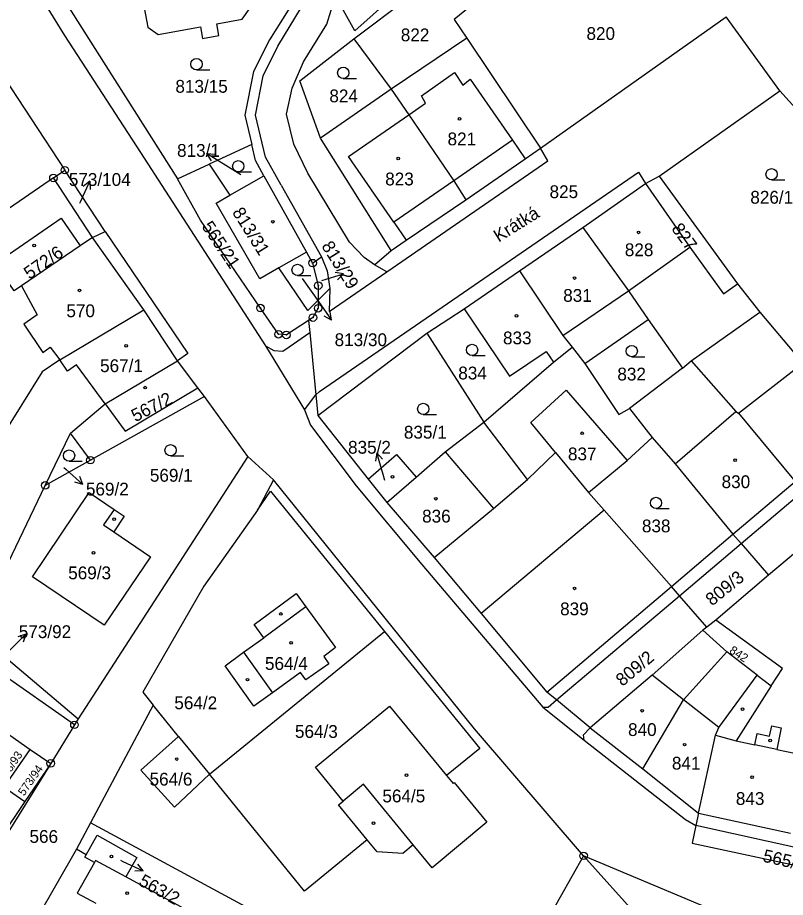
# Model space of a CAD drawing. Extents: x -776701 to -776081, y -974398 to -973771.
# Drawn here: x -776342.5 to -776240.6, y -974065.8 to -973949 of the extents above; entities that cross this region are included whole.
import ezdxf

# ---------------------------------------------------------------- set-up
doc = ezdxf.new("R2010")
doc.units = 0
for name, color, linetype in [('Hranice parcel', 7, 'Continuous'), ('Parcelní čísla', 7, 'Continuous'), ('Pop  PČ popisy', 7, 'Continuous'), ('Vnitřní kresba', 7, 'Continuous'), ('Značky bodu BP', 7, 'Continuous'), ('Značky budov', 7, 'Continuous'), ('Značky kultur', 7, 'Continuous')]:
    doc.layers.add(name, color=color, linetype=linetype)

msp = doc.modelspace()

# ---------------------------------------------------------------- linework, layer by layer
at = {"layer": 'Hranice parcel'}
for p, q in [((-776297.88, -973951.84), (-776284.08, -973941.43)), ((-776338.75, -973942.85), (-776321.28, -973970.41)), ((-776273.08, -973966.36), (-776248.44, -973948.9)), ((-776241.31, -973958.73), (-776248.44, -973948.9)), ((-776297.88, -973951.84), (-776292.9, -973958.5)), ((-776282.89, -973951.76), (-776292.9, -973958.5)), ((-776282.89, -973951.76), (-776273.08, -973966.36)), ((-776346.46, -973953.73), (-776336.24, -973969.27)), ((-776292.9, -973958.5), (-776302.3, -973965)), ((-776257.34, -973970.07), (-776241.31, -973958.73)), ((-776311.42, -973965.87), (-776317.09, -973968.48)), ((-776292.91, -973979.92), (-776302.3, -973965)), ((-776337.75, -973970.3), (-776336.24, -973969.27)), ((-776321.28, -973970.41), (-776317.09, -973968.48)), ((-776317.09, -973968.48), (-776314.32, -973972.59)), ((-776332.57, -973978.19), (-776337.75, -973970.3)), ((-776318.24, -973975.91), (-776321.28, -973970.41)), ((-776314.32, -973972.59), (-776309.8, -973970.01)), ((-776309.8, -973970.01), (-776304.16, -973980.15)), ((-776259.16, -973971.03), (-776257.34, -973970.07)), ((-776257.34, -973970.07), (-776246.94, -973984.38)), ((-776267.49, -973976.87), (-776259.16, -973971.03)), ((-776275.87, -973982.65), (-776267.49, -973976.87)), ((-776332.57, -973978.19), (-776334.21, -973979.31)), ((-776325.75, -973987.82), (-776332.57, -973978.19)), ((-776295.13, -973981.83), (-776292.91, -973979.92)), ((-776304.16, -973980.15), (-776307.81, -973982.25)), ((-776304.16, -973980.15), (-776303.35, -973981.61)), ((-776283.21, -973987.69), (-776275.87, -973982.65)), ((-776246.94, -973984.38), (-776243.98, -973988.1)), ((-776301.05, -973985), (-776302.6, -973986.53)), ((-776302.6, -973986.53), (-776302.61, -973987.61)), ((-776336.89, -973994.45), (-776325.75, -973987.82)), ((-776321.3, -973994.6), (-776325.75, -973987.82)), ((-776288.2, -973990.91), (-776283.21, -973987.69)), ((-776253.07, -973994.57), (-776243.98, -973988.1)), ((-776267.2, -973994.95), (-776258.81, -973989.08)), ((-776258.81, -973989.08), (-776254.25, -973995.57)), ((-776302.67, -974001.86), (-776288.2, -973990.91)), ((-776288.2, -973990.91), (-776280.61, -974002.73)), ((-776271.38, -973994.77), (-776268.9, -973992.75)), ((-776268.9, -973992.75), (-776267.2, -973994.95)), ((-776330.9, -974000.3), (-776321.3, -973994.6)), ((-776280.61, -974002.73), (-776271.38, -973994.77)), ((-776254.25, -973995.57), (-776253.07, -973994.57)), ((-776254.25, -973995.57), (-776261.3, -974000.9)), ((-776317.7, -973999.3), (-776332.85, -974007.77)), ((-776311.96, -974007.29), (-776317.7, -973999.3)), ((-776335.5, -974004.17), (-776330.9, -974000.3)), ((-776261.3, -974000.9), (-776258.29, -974004.76)), ((-776302.67, -974001.86), (-776295.97, -974010.29)), ((-776274.81, -974010.35), (-776280.61, -974002.73)), ((-776338.84, -974011.12), (-776335.5, -974004.17)), ((-776332.85, -974007.77), (-776335.5, -974004.17)), ((-776332.85, -974007.77), (-776338.84, -974011.12)), ((-776311.96, -974007.29), (-776334.46, -974042.11)), ((-776308.52, -974010.36), (-776311.96, -974007.29)), ((-776308.52, -974010.36), (-776310.67, -974014.4)), ((-776295.97, -974010.29), (-776293.49, -974013.38)), ((-776293.49, -974013.38), (-776289.58, -974010.03)), ((-776348.16, -974030.54), (-776338.84, -974011.12)), ((-776247.57, -974017.58), (-776239.27, -974010.62)), ((-776293.49, -974013.38), (-776287.2, -974020.7)), ((-776231.58, -974013.49), (-776242.81, -974023.05)), ((-776255.71, -974024.55), (-776247.57, -974017.58)), ((-776242.81, -974023.05), (-776249.83, -974029.02)), ((-776272.25, -974038.56), (-776255.71, -974024.55)), ((-776249.83, -974029.02), (-776251.01, -974029.93)), ((-776251.01, -974029.93), (-776251.54, -974030.34)), ((-776248.36, -974033.23), (-776251.54, -974030.34)), ((-776348.16, -974030.54), (-776334.46, -974042.11)), ((-776317.05, -974049.45), (-776293.78, -974030.52)), ((-776334.96, -974042.91), (-776348.94, -974033.12)), ((-776244.32, -974036.32), (-776248.36, -974033.23)), ((-776324.49, -974040.31), (-776332.81, -974055.91)), ((-776321.13, -974044.44), (-776324.49, -974040.31)), ((-776334.96, -974042.91), (-776338.11, -974048.02)), ((-776334.46, -974042.11), (-776334.96, -974042.91)), ((-776343.54, -974044.26), (-776340.85, -974046.16)), ((-776266.49, -974043.3), (-776259.49, -974048.74)), ((-776321.13, -974044.44), (-776317.05, -974049.45)), ((-776344.27, -974051.19), (-776340.85, -974046.16)), ((-776340.85, -974046.16), (-776338.11, -974048.02)), ((-776338.11, -974048.02), (-776344.68, -974058.65)), ((-776338.11, -974048.02), (-776341.55, -974053.07)), ((-776259.49, -974048.74), (-776252.12, -974054.65)), ((-776317.05, -974049.45), (-776321.68, -974053.83)), ((-776344.27, -974051.19), (-776341.55, -974053.07)), ((-776296.1, -974058.19), (-776299.93, -974053.54)), ((-776252.12, -974054.65), (-776252.47, -974056.28)), ((-776252.12, -974054.65), (-776239.9, -974057.27)), ((-776332.81, -974055.91), (-776334.7, -974059.4)), ((-776309.4, -974068.57), (-776332.81, -974055.91)), ((-776294.79, -974059.76), (-776296.1, -974058.19)), ((-776334.7, -974059.4), (-776344.3, -974076.22)), ((-776333.4, -974060.17), (-776334.7, -974059.4)), ((-776267.37, -974060.3), (-776282.47, -974086.79)), ((-776248.62, -974068.16), (-776267.37, -974060.3)), ((-776246.97, -974083.03), (-776267.37, -974060.3))]:
    msp.add_line(p, q, dxfattribs=at)
for points in [[(-776313.98, -973911.05), (-776297.73, -973912.06), (-776288.32, -973927.36), (-776286.35, -973940.59), (-776297.76, -973950.76), (-776300.32, -973946.11)], [(-776348.8, -973929.48), (-776343.01, -973940.47), (-776336.28, -973951.4), (-776326.2, -973966.93), (-776309.58, -973992.58), (-776304.42, -974001.08), (-776303.62, -974003.12), (-776297.56, -974011.17), (-776288.84, -974021.6), (-776272.77, -974040.55), (-776267.29, -974044.95), (-776253.84, -974055.49), (-776252.47, -974056.28)], [(-776327.4, -973940.82), (-776326.45, -973946.13), (-776326.01, -973946.05), (-776325.24, -973950.29), (-776323.84, -973951.26), (-776318.22, -973950.24), (-776317.95, -973951.77), (-776315.78, -973951.38), (-776316.05, -973949.85), (-776312.7, -973949.24), (-776311.73, -973947.84), (-776312.5, -973943.6), (-776311.81, -973943.48), (-776304.89, -973942.24)], [(-776304.89, -973942.24), (-776305.41, -973945.33), (-776306.38, -973947.66), (-776309.08, -973951.97), (-776311.19, -973956.17), (-776312.36, -973961.96), (-776311.42, -973965.87)], [(-776295.13, -973981.83), (-776296.49, -973980.88), (-776298.45, -973978.83), (-776303.97, -973969.66), (-776305.82, -973965.81), (-776306.81, -973961.85), (-776306.08, -973958.37), (-776304.57, -973954.89), (-776301.44, -973949.87), (-776300.32, -973946.11)], [(-776280.81, -973946.19), (-776284.56, -973949.27), (-776282.89, -973951.76)], [(-776302.3, -973965), (-776305.05, -973957.4), (-776297.88, -973951.84)], [(-776292.9, -973958.5), (-776290.55, -973961.91), (-776284.59, -973970.68), (-776283.02, -973973.23)], [(-776230.92, -974003.68), (-776213.75, -973989.29), (-776241.31, -973958.73)], [(-776309.8, -973970.01), (-776310.91, -973967.99), (-776311.42, -973965.87)], [(-776283.02, -973973.23), (-776275.12, -973967.75), (-776273.08, -973966.36)], [(-776332.57, -973978.19), (-776330.9, -973977.4), (-776336.24, -973969.27)], [(-776337.75, -973970.3), (-776338.32, -973970.69), (-776348.3, -973977.53), (-776374.53, -974010.37)], [(-776259.16, -973971.03), (-776253.26, -973979.51), (-776248.81, -973985.69), (-776246.94, -973984.38)], [(-776307.81, -973982.25), (-776310.35, -973983.7), (-776316.15, -973973.64), (-776314.32, -973972.59)], [(-776292.91, -973979.92), (-776290.92, -973978.58), (-776283.02, -973973.23)], [(-776342.98, -973985.31), (-776345.48, -973981.66), (-776336.71, -973975.66), (-776334.21, -973979.31)], [(-776303.87, -973989.21), (-776306.83, -973991.14), (-776307.87, -973991.06), (-776310.26, -973987.58), (-776318.24, -973975.91)], [(-776267.49, -973976.87), (-776261.42, -973985.31), (-776258.81, -973989.08)], [(-776334.21, -973979.31), (-776342, -973984.63), (-776342.98, -973985.31)], [(-776303.35, -973981.61), (-776302.17, -973980.77), (-776301.41, -973982.63), (-776301.05, -973985)], [(-776302.6, -973986.53), (-776304, -973987.9), (-776307.81, -973982.25)], [(-776303.35, -973981.61), (-776302.59, -973984.6), (-776302.6, -973986.53)], [(-776301.05, -973985), (-776301.15, -973988.05), (-776293.49, -973982.77), (-776295.13, -973981.83)], [(-776275.87, -973982.65), (-776270.15, -973991.2), (-776268.9, -973992.75)], [(-776302.61, -973987.61), (-776303.3, -973988.84), (-776303.87, -973989.21)], [(-776283.21, -973987.69), (-776277.23, -973996.63), (-776272.33, -973993.35), (-776271.38, -973994.77)], [(-776243.98, -973988.1), (-776238.25, -973994.88), (-776230.92, -974003.68)], [(-776303.87, -973989.21), (-776303.72, -973990.83), (-776302.93, -973999.08), (-776302.67, -974001.86)], [(-776336.89, -973994.45), (-776339.24, -973996.03), (-776344.63, -974004.7)], [(-776330.9, -974000.3), (-776334.7, -973995.1), (-776335.9, -973995.95), (-776336.89, -973994.45)], [(-776317.7, -973999.3), (-776318.56, -973998.17), (-776321.3, -973994.6)], [(-776267.2, -973994.95), (-776262.7, -974001.7), (-776261.3, -974000.9)], [(-776253.07, -973994.57), (-776247.18, -974001.31), (-776246.82, -974001.54), (-776239.27, -974010.62)], [(-776289.58, -974010.03), (-776285.74, -974006.66), (-776280.61, -974002.73)], [(-776266.72, -974012.05), (-776261.58, -974007.81), (-776258.29, -974004.76)], [(-776258.29, -974004.76), (-776255.23, -974008.26), (-776247.57, -974017.58)], [(-776274.81, -974010.35), (-776271.09, -974006.74), (-776266.72, -974012.05)], [(-776295.97, -974010.29), (-776292.19, -974007.01), (-776289.58, -974010.03)], [(-776267.37, -974060.3), (-776281.86, -974043.45), (-776308.52, -974010.36)], [(-776287.2, -974020.7), (-776279.35, -974014.2), (-776274.81, -974010.35)], [(-776340.54, -974023.25), (-776332.99, -974012.08), (-776329.69, -974014.3), (-776328.36, -974015.19), (-776329.75, -974017.28), (-776324.86, -974020.59), (-776331.02, -974029.69), (-776340.54, -974023.25)], [(-776310.67, -974014.4), (-776308.92, -974011.9), (-776293.78, -974030.52)], [(-776266.72, -974012.05), (-776264.63, -974014.42), (-776255.71, -974024.55)], [(-776310.67, -974014.4), (-776317.77, -974024.51), (-776325.89, -974038.59), (-776324.49, -974040.31)], [(-776247.57, -974017.58), (-776246.47, -974018.84), (-776242.81, -974023.05)], [(-776287.2, -974020.7), (-776280.99, -974028.12), (-776272.25, -974038.56)], [(-776300.3, -974032.65), (-776301.87, -974033.84), (-776301.2, -974034.79), (-776304.23, -974036.93), (-776304.95, -974035.94), (-776308.67, -974038.65), (-776311.16, -974040.45), (-776314.95, -974035.08), (-776312.51, -974033.28), (-776309.82, -974031.36), (-776311.09, -974029.58), (-776305.51, -974025.48), (-776304.23, -974027.24), (-776300.3, -974032.65)], [(-776251.01, -974029.93), (-776254.65, -974025.76), (-776255.71, -974024.55)], [(-776244.32, -974036.32), (-776242.45, -974037.75), (-776240.95, -974035.41), (-776249.83, -974029.02)], [(-776251.54, -974030.34), (-776258.26, -974036.31), (-776266.49, -974043.3)], [(-776293.78, -974030.52), (-776281.16, -974046.04), (-776285.56, -974049.62)], [(-776259.49, -974048.74), (-776254.11, -974039.57), (-776248.36, -974033.23)], [(-776252.12, -974054.65), (-776249.88, -974044.26), (-776249.42, -974043.26), (-776244.32, -974036.32)], [(-776266.49, -974043.3), (-776270.99, -974039.59), (-776272.25, -974038.56)], [(-776299.93, -974053.54), (-776299.29, -974053.02), (-776302.98, -974048.54), (-776293.15, -974040.43), (-776285.56, -974049.62)], [(-776321.68, -974053.83), (-776326.17, -974048.92), (-776321.13, -974044.44)], [(-776296.1, -974058.19), (-776304.44, -974064.97), (-776317.05, -974049.45)], [(-776285.56, -974049.62), (-776284.68, -974050.68), (-776284.56, -974050.58), (-776280.21, -974055.85), (-776287.46, -974061.89), (-776289.98, -974058.83), (-776291.39, -974059.99), (-776294.79, -974059.76)], [(-776341.55, -974053.07), (-776344.92, -974058.03), (-776347.66, -974056.15)], [(-776252.47, -974056.28), (-776252.98, -974058.63), (-776229.18, -974063.72), (-776228.71, -974061.56)], [(-776333.4, -974060.17), (-776331.95, -974057.57), (-776326.69, -974060.51), (-776328.13, -974063.09)], [(-776332.31, -974061.19), (-776333.57, -974060.48), (-776333.4, -974060.17)], [(-776332.31, -974061.19), (-776334.6, -974065.25), (-776332.13, -974066.56)], [(-776328.13, -974063.09), (-776332.15, -974060.9), (-776332.31, -974061.19)], [(-776322.64, -974071.77), (-776320.25, -974067.39), (-776328.13, -974063.09)]]:
    msp.add_lwpolyline(points, dxfattribs=at)
at = {"layer": 'Pop  PČ popisy'}
for p, q in [((-776314.86, -973968.64), (-776317.41, -973967.05)), ((-776317.41, -973967.05), (-776316.29, -973967.16)), ((-776317.41, -973967.05), (-776316.82, -973968.01)), ((-776312.87, -973969.89), (-776314.86, -973968.64)), ((-776334.16, -973973.47), (-776332.94, -973970.73)), ((-776332.94, -973970.73), (-776333.8, -973971.44)), ((-776332.94, -973970.73), (-776332.89, -973971.85)), ((-776334.25, -973973.66), (-776334.16, -973973.47)), ((-776302.11, -973983.92), (-776299.24, -973983.04)), ((-776299.24, -973983.04), (-776300.34, -973982.86)), ((-776299.24, -973983.04), (-776300.05, -973983.81)), ((-776304.71, -973983.67), (-776302.57, -973986.71)), ((-776302.11, -973983.92), (-776302.12, -973983.92)), ((-776302.57, -973986.71), (-776300.85, -973989.17)), ((-776300.85, -973989.17), (-776301.01, -973988.06)), ((-776300.85, -973989.17), (-776301.83, -973988.64)), ((-776294.81, -974006.81), (-776295.01, -974007.91)), ((-776293.98, -974009.69), (-776294.81, -974006.81)), ((-776294.81, -974006.81), (-776294.05, -974007.63)), ((-776336.36, -974008.73), (-776336.07, -974008.99)), ((-776336.07, -974008.99), (-776333.84, -974011)), ((-776333.84, -974011), (-776334.25, -974009.96)), ((-776293.76, -974010.45), (-776293.98, -974009.69)), ((-776333.84, -974011), (-776334.92, -974010.7)), ((-776343.55, -974032.99), (-776341.43, -974030.87)), ((-776341.43, -974030.87), (-776342.49, -974031.22)), ((-776341.43, -974030.87), (-776341.78, -974031.93)), ((-776328.86, -974060.89), (-776328.56, -974061.03)), ((-776328.56, -974061.03), (-776325.84, -974062.3)), ((-776325.84, -974062.3), (-776326.54, -974061.42)), ((-776325.84, -974062.3), (-776326.96, -974062.33))]:
    msp.add_line(p, q, dxfattribs=at)
at = {"layer": 'Vnitřní kresba'}
for p, q in [((-776307.95, -973952.83), (-776304.82, -973947.64)), ((-776309.89, -973956.74), (-776307.95, -973952.83)), ((-776310.93, -973961.96), (-776309.89, -973956.74)), ((-776288.9, -973959.4), (-776284.53, -973956.3)), ((-776284.53, -973956.3), (-776283.4, -973958)), ((-776283.4, -973958), (-776282.45, -973957.2)), ((-776282.45, -973957.2), (-776276.79, -973965.28)), ((-776288.34, -973960.39), (-776288.9, -973959.4)), ((-776290.55, -973961.91), (-776288.34, -973960.39)), ((-776309.58, -973967.56), (-776310.93, -973961.96)), ((-776298.6, -973967.47), (-776290.55, -973961.91)), ((-776276.79, -973965.28), (-776284.59, -973970.68)), ((-776276.79, -973965.28), (-776275.12, -973967.75)), ((-776272.13, -973968.03), (-776273.08, -973966.36)), ((-776307.52, -973971.26), (-776309.58, -973967.56)), ((-776292.58, -973976.18), (-776298.6, -973967.47)), ((-776293.49, -973982.77), (-776272.13, -973968.03)), ((-776302.45, -973998.67), (-776260.07, -973969.53)), ((-776260.07, -973969.53), (-776259.16, -973971.03)), ((-776284.59, -973970.68), (-776292.58, -973976.18)), ((-776307.52, -973971.26), (-776302.17, -973980.77)), ((-776292.58, -973976.18), (-776290.92, -973978.58)), ((-776330.9, -973977.4), (-776319.9, -973993.6)), ((-776261.42, -973985.31), (-776253.26, -973979.51)), ((-776342, -973984.63), (-776339.89, -973988.49)), ((-776270.15, -973991.2), (-776261.42, -973985.31)), ((-776339.89, -973988.49), (-776341.67, -973989.72)), ((-776341.67, -973989.72), (-776339.18, -973993.46)), ((-776246.47, -974018.84), (-776212.73, -973990.29)), ((-776339.18, -973993.46), (-776338.18, -973992.79)), ((-776338.18, -973992.79), (-776336.89, -973994.45)), ((-776319.9, -973993.6), (-776321.3, -973994.6)), ((-776246.82, -974001.54), (-776238.25, -973994.88)), ((-776328.24, -974003.93), (-776318.56, -973998.17)), ((-776302.45, -973998.67), (-776302.93, -973999.08)), ((-776274.36, -974002.77), (-776269.67, -973998.49)), ((-776269.67, -973998.49), (-776261.58, -974007.81)), ((-776304.42, -974001.08), (-776302.93, -973999.08)), ((-776330.9, -974000.3), (-776328.24, -974003.93)), ((-776255.23, -974008.26), (-776247.18, -974001.31)), ((-776271.09, -974006.74), (-776274.36, -974002.77)), ((-776285.74, -974006.66), (-776279.35, -974014.2)), ((-776264.63, -974014.42), (-776280.99, -974028.12)), ((-776254.65, -974025.76), (-776246.47, -974018.84)), ((-776270.99, -974039.59), (-776254.65, -974025.76)), ((-776304.23, -974027.24), (-776309.82, -974031.36)), ((-776312.51, -974033.28), (-776308.67, -974038.65)), ((-776254.11, -974039.57), (-776258.26, -974036.31)), ((-776242.45, -974037.75), (-776247.13, -974045.01)), ((-776249.42, -974043.26), (-776254.11, -974039.57)), ((-776242.68, -974044.41), (-776242.38, -974043.05)), ((-776242.38, -974043.05), (-776241.14, -974043.31)), ((-776267.39, -974044.25), (-776266.49, -974043.3)), ((-776267.29, -974044.95), (-776267.39, -974044.25)), ((-776249.88, -974044.26), (-776247.13, -974045.01)), ((-776244.63, -974045.54), (-776244.31, -974044.06)), ((-776244.31, -974044.06), (-776242.68, -974044.41)), ((-776241.14, -974043.31), (-776241.74, -974046.16)), ((-776247.13, -974045.01), (-776244.63, -974045.54)), ((-776241.74, -974046.16), (-776244.63, -974045.54)), ((-776241.74, -974046.16), (-776237.86, -974046.99)), ((-776296.61, -974050.8), (-776299.29, -974053.02)), ((-776289.98, -974058.83), (-776296.61, -974050.8)), ((-776228.69, -974061.51), (-776252.47, -974056.28))]:
    msp.add_line(p, q, dxfattribs=at)
for points in [[(-776309.58, -973992.58), (-776308.49, -973993.22), (-776307.31, -973993.31), (-776306.47, -973992.73), (-776303.72, -973990.83)], [(-776329.69, -974014.3), (-776331.09, -974016.37), (-776329.75, -974017.28)], [(-776272.77, -974040.55), (-776272.06, -974040.55), (-776270.99, -974039.59)]]:
    msp.add_lwpolyline(points, dxfattribs=at)
at = {"layer": 'Značky bodu BP'}
for centre, radius in [((-776336.24, -973969.27), 0.5), ((-776336.24, -973969.27), 0.0303), ((-776337.75, -973970.3), 0.5), ((-776337.75, -973970.3), 0.0303), ((-776303.35, -973981.61), 0.5), ((-776303.35, -973981.61), 0.0303), ((-776302.59, -973984.6), 0.5), ((-776302.59, -973984.6), 0.0303), ((-776310.26, -973987.58), 0.5), ((-776302.61, -973987.61), 0.5), ((-776310.26, -973987.58), 0.0303), ((-776302.61, -973987.61), 0.0303), ((-776303.3, -973988.84), 0.5), ((-776303.3, -973988.84), 0.0303), ((-776307.87, -973991.06), 0.5), ((-776306.83, -973991.14), 0.5), ((-776307.87, -973991.06), 0.0303), ((-776306.83, -973991.14), 0.0303), ((-776332.85, -974007.77), 0.5), ((-776332.85, -974007.77), 0.0303), ((-776338.84, -974011.12), 0.5), ((-776338.84, -974011.12), 0.0303), ((-776334.96, -974042.91), 0.5), ((-776334.96, -974042.91), 0.0303), ((-776338.11, -974048.02), 0.5), ((-776338.11, -974048.02), 0.0303), ((-776267.37, -974060.3), 0.5), ((-776267.37, -974060.3), 0.0303)]:
    msp.add_circle(centre, radius, dxfattribs=at)
at = {"layer": 'Značky budov'}
for centre in [(-776283.83, -973962.46), (-776291.97, -973967.71), (-776308.62, -973976.11), (-776260.07, -973977.53), (-776340.32, -973979.28), (-776268.56, -973983.59), (-776334.28, -973985.23), (-776276.27, -973988.62), (-776328.09, -973992.6), (-776325.58, -973998.14), (-776267.57, -974004.2), (-776247.27, -974007.77), (-776292.73, -974009.99), (-776286.98, -974012.89), (-776329.68, -974015.61), (-776332.42, -974020.07), (-776268.56, -974024.79), (-776307.57, -974028.19), (-776306.21, -974032.03), (-776311.98, -974036.91), (-776259.6, -974041.03), (-776246.26, -974040.82), (-776253.96, -974045.54), (-776242.61, -974044.98), (-776321.39, -974047.45), (-776290.89, -974049.6), (-776245.01, -974049.86), (-776295.25, -974055.96), (-776330.06, -974060.39), (-776327.96, -974065.26)]:
    msp.add_circle(centre, 0.175, dxfattribs=at)
at = {"layer": 'Značky kultur'}
for p, q in [((-776318.76, -973955.95), (-776317.01, -973955.95)), ((-776299.28, -973957.1), (-776297.53, -973957.1)), ((-776313.21, -973969.5), (-776311.46, -973969.5)), ((-776242.41, -973970.56), (-776240.66, -973970.56)), ((-776305.34, -973983.26), (-776303.59, -973983.26)), ((-776282.17, -973993.89), (-776280.42, -973993.89)), ((-776260.98, -973994.03), (-776259.23, -973994.03)), ((-776288.65, -974001.72), (-776286.9, -974001.72)), ((-776335.68, -974007.92), (-776333.93, -974007.92)), ((-776322.2, -974007.21), (-776320.45, -974007.21)), ((-776257.76, -974014.19), (-776256.01, -974014.19))]:
    msp.add_line(p, q, dxfattribs=at)
for centre in [(-776318.76, -973955.2), (-776299.28, -973956.35), (-776313.21, -973968.75), (-776242.41, -973969.81), (-776305.34, -973982.51), (-776282.17, -973993.14), (-776260.98, -973993.28), (-776288.65, -974000.97), (-776322.2, -974006.46), (-776335.68, -974007.17), (-776257.76, -974013.44)]:
    msp.add_circle(centre, 0.75, dxfattribs=at)

# ---------------------------------------------------------------- texts
at = {"layer": 'Parcelní čísla'}
for s, p in [('822', (-776291.64, -973952.16)), ('820', (-776266.99, -973951.98)), ('813/15', (-776321.56, -973958.99)), ('824', (-776301.12, -973960.26)), ('821', (-776285.43, -973965.97)), ('813/1', (-776321.34, -973967.5)), ('573/104', (-776335.71, -973971.36)), ('823', (-776293.71, -973971.29)), ('825', (-776271.89, -973972.98)), ('826/1', (-776245.24, -973973.72)), ('828', (-776261.9, -973980.69)), ('831', (-776270.08, -973986.75)), ('570', (-776336.03, -973988.79)), ('813/30', (-776300.42, -973992.63)), ('833', (-776278.07, -973992.39)), ('567/1', (-776331.56, -973996.08)), ('834', (-776284.01, -973997.05)), ('832', (-776262.89, -973997.19)), ('835/1', (-776291.23, -974004.91)), ('835/2', (-776298.64, -974006.91)), ('837', (-776269.45, -974007.79)), ('569/1', (-776324.95, -974010.63)), ('830', (-776249.05, -974011.48)), ('569/2', (-776333.44, -974012.46)), ('836', (-776288.81, -974016.05)), ('838', (-776259.63, -974017.35)), ('569/3', (-776335.79, -974023.58)), ('839', (-776270.49, -974028.36)), ('573/92', (-776342.35, -974031.39)), ('564/4', (-776309.67, -974035.62)), ('564/2', (-776321.7, -974040.83)), ('564/3', (-776305.69, -974044.64)), ('840', (-776261.47, -974044.39)), ('841', (-776255.65, -974048.85)), ('564/6', (-776324.99, -974050.97)), ('564/5', (-776294.08, -974053.2)), ('843', (-776247.16, -974053.54)), ('566', (-776340.93, -974058.58))]:
    msp.add_text(s, height=1.7, dxfattribs=at).set_placement(p)
for s, height, rotation, p in [('813/31', 1.7, 302, (-776314.08, -973974.86)), ('565/21', 1.7, 304, (-776318.14, -973976.75)), ('827', 1.7, 306, (-776255.78, -973977.06)), ('813/29', 1.7, 302, (-776302.23, -973979.34)), ('572/6', 1.7, 35, (-776340.93, -973983.84)), ('567/2', 1.7, 27, (-776326.87, -974002.74)), ('809/3', 1.7, 39, (-776250.32, -974027.2)), ('842', 1.139, 327, (-776248.13, -974033.29)), ('809/2', 1.7, 40, (-776262.22, -974037.88)), ('573/93', 1.1, 56, (-776344.31, -974050.61)), ('573/94', 1.1, 55, (-776341.65, -974052.42)), ('565/6', 1.7, 347, (-776243.68, -974061.05)), ('563/2', 1.7, 331, (-776326.56, -974064.12))]:
    msp.add_text(s, height=height, rotation=rotation, dxfattribs=at).set_placement(p)
at = {"layer": 'Pop  PČ popisy'}
msp.add_text('Krátká', height=1.7, rotation=32, dxfattribs=at).set_placement((-776278.65, -973978.9))

doc.saveas('drawing.dxf')
